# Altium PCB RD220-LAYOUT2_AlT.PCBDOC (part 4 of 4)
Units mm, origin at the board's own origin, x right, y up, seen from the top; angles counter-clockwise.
Board outline 250 x 145 mm, 4 copper layers (TOP, Mid-Layer 1, Mid-Layer 2, BOTTOM), stack 0.711 mm thick; 497 components, 207 nets, 1178 pads, 436 vias.
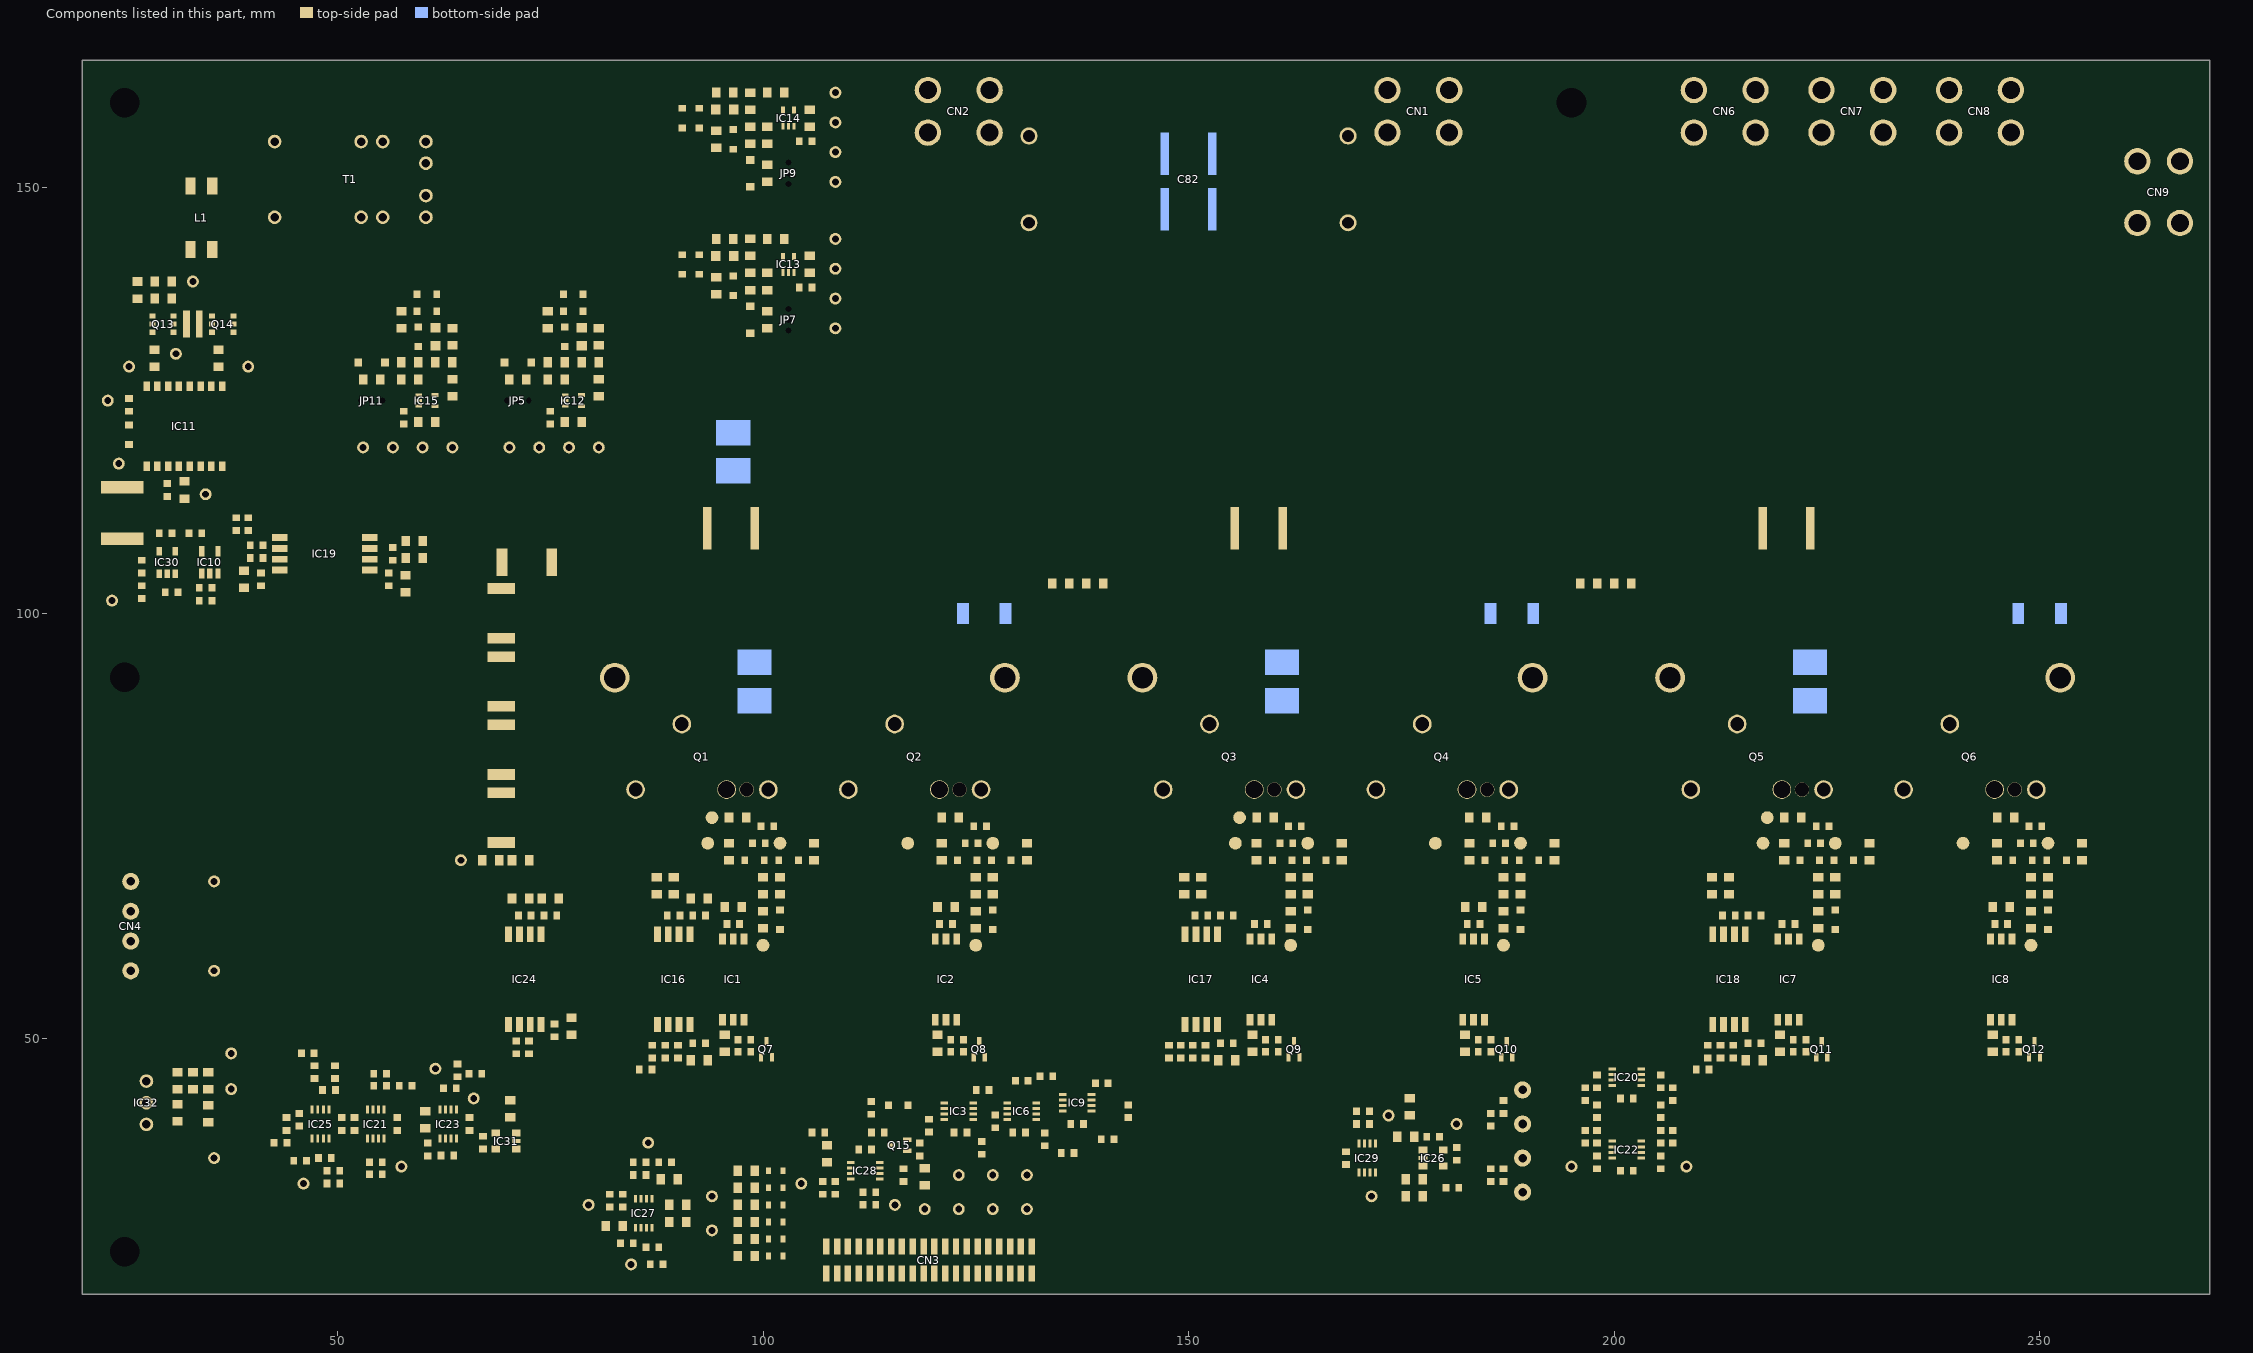
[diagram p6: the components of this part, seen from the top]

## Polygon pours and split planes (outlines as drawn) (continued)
GND_D on TOP "TOP129" (solid, pour order 186): 118.25,37.35 cw(c118.25,37.5) 118.1,37.5 118.1,37.9 cw(c118.25,37.9) 118.25,38.05 119.75,38.05 cw(c119.75,37.9) 119.9,37.9 119.9,37.5 cw(c119.75,37.5) 119.75,37.35
GND_D on TOP "TOP130" (solid, pour order 187): 118.062,37.5 cw(c118.062,37.65) 117.956,37.544 117.6,37.9 116.75,37.9 cw(c116.75,38.05) 116.6,38.05 116.6,38.25 cw(c116.75,38.25) 116.75,38.4 117.688,38.4 cw(c117.688,38.25) 117.794,38.356 118.394,37.756 cw(c118.288,37.65) 118.288,37.5
GND_D on TOP "TOP131" (solid, pour order 188): 116.9,38.7 cw(c116.9,38.85) 116.75,38.85 116.75,39.651 cw(c116.9,39.651) 116.794,39.757 117.368,40.332 117.369,40.333 ccw(c117.05,40.65) 117.5,40.65 117.5,40.85 cw(c117.65,40.85) 117.65,41 118.6,41 cw(c118.6,40.85) 118.75,40.85 118.75,38.85 cw(c118.6,38.85) 118.6,38.7
GND_D on TOP "TOP132" (solid, pour order 189): 117.9,38.7 cw(c117.9,38.85) 117.75,38.85 117.75,39.3 cw(c117.9,39.3) 117.9,39.45 119.7,39.45 cw(c119.7,39.3) 119.85,39.3 119.85,38.85 cw(c119.7,38.85) 119.7,38.7
GND_D on TOP "TOP133" (solid, pour order 190): 118.25,37.6 cw(c118.25,37.75) 118.1,37.75 118.1,38.7 117.4,38.7 cw(c117.4,38.85) 117.25,38.85 117.25,39.85 cw(c117.4,39.85) 117.4,40 118.6,40 cw(c118.6,39.85) 118.75,39.85 118.75,37.75 cw(c118.6,37.75) 118.6,37.6
GND_D on TOP "TOP134" (solid, pour order 191): 25 vertices, not listed, extent 119.15,30.9 121.732,38.35
GND_D on TOP "TOP135" (solid, pour order 192): 22 vertices, not listed, extent 122.3,35 125.701,38.25
GND_D on TOP "TOP136" (solid, pour order 193): 125.35,36.55 cw(c125.5,36.55) 125.5,36.7 126,36.7 cw(c126,36.55) 126.15,36.55 126.15,36.049 cw(c126,36.049) 126.106,35.942 125.606,35.442 cw(c125.5,35.549) 125.35,35.549
GND_D on TOP "TOP137" (solid, pour order 194): 124.211,36.2 cw(c124.211,36.35) 124.105,36.244 123.644,36.705 cw(c123.75,36.811) 123.6,36.811 123.6,37.45 cw(c123.75,37.45) 123.75,37.6 124.25,37.6 cw(c124.25,37.45) 124.4,37.45 124.4,36.85 125.85,36.85 cw(c125.85,36.7) 126,36.7 126,36.35 cw(c125.85,36.35) 125.85,36.2
GND_D on TOP "TOP138" (solid, pour order 195): 123.7,37.05 cw(c123.7,37.2) 123.55,37.2 123.55,40.55 cw(c123.7,40.55) 123.7,40.7 123.8,40.7 cw(c123.8,40.55) 123.95,40.55 123.95,40.4 ccw(c124.3,40.4) 124.23,40.057 cw(c124.2,39.91) 124.35,39.91 124.35,37.2 cw(c124.2,37.2) 124.2,37.05
GND_D on TOP "TOP139" (solid, pour order 196): 137.4,38.3 cw(c137.4,38.45) 137.25,38.45 137.25,41.1 cw(c137.4,41.1) 137.4,41.25 137.782,41.25 cw(c137.782,41.1) 137.908,41.183 ccw(c138.2,41.375) 137.99,41.095 cw(c137.9,40.975) 138.05,40.975 138.05,38.45 cw(c137.9,38.45) 137.9,38.3
GND_D on TOP "TOP140" (solid, pour order 197): 137.25,37 ccw(c136.9,37) 136.9,37.35 cw(c136.9,37.5) 136.78,37.59 ccw(c135.9,38.25) 137,38.25 137,39.1 cw(c137.15,39.1) 137.15,39.25 138.9,39.25 cw(c138.9,39.1) 139.05,39.1 139.05,38.199 cw(c138.9,38.199) 139.006,38.092 137.506,36.593 cw(c137.4,36.699) 137.25,36.699
GND_D on TOP "TOP141" (solid, pour order 198): 137.1,44.35 cw(c137.1,44.5) 136.95,44.5 136.95,45.1 cw(c137.1,45.1) 137.1,45.25 139.15,45.25 cw(c139.15,45.1) 139.3,45.1 139.3,44.5 cw(c139.15,44.5) 139.15,44.35
GND_D on TOP "TOP142" (solid, pour order 199): 23 vertices, not listed, extent 136.55,40.748 138.35,45.3
GND_D on TOP "TOP143" (solid, pour order 200): 130.9,43.45 cw(c130.9,43.6) 130.75,43.6 130.75,45.2 cw(c130.9,45.2) 130.9,45.35 131.4,45.35 cw(c131.4,45.2) 131.55,45.2 131.55,43.6 cw(c131.4,43.6) 131.4,43.45
GND_D on TOP "TOP144" (solid, pour order 201): 132.3,44.2 cw(c132.3,44.35) 132.15,44.35 132.15,45.7 cw(c132.3,45.7) 132.3,45.85 132.8,45.85 cw(c132.8,45.7) 132.95,45.7 132.95,44.549 cw(c132.8,44.549) 132.906,44.443 132.707,44.244 cw(c132.601,44.35) 132.601,44.2
GND_D on TOP "TOP145" (solid, pour order 202): 123,43.55 cw(c123,43.7) 122.85,43.7 122.85,44.15 cw(c123,44.15) 123,44.3 123.088,44.3 ccw(c123.088,44.75) 123.386,44.412 cw(c123.485,44.3) 123.485,44.45 125.1,44.45 cw(c125.1,44.3) 125.25,44.3 125.25,43.7 cw(c125.1,43.7) 125.1,43.55
GND_D on TOP "TOP146" (solid, pour order 203): 31 vertices, not listed, extent 122.543,39.748 124.35,44.45
GND_D on TOP "TOP147" (solid, pour order 204): 127 vertices, not listed, extent 131.6,27.3 175.1,43.8
GND_A on TOP "TOP148" (solid, pour order 205): 249.95,46.5 cw(c249.95,46.65) 249.8,46.65 249.8,48.9 cw(c249.95,48.9) 249.95,49.05 250.15,49.05 cw(c250.15,48.9) 250.3,48.9 250.3,46.65 cw(c250.15,46.65) 250.15,46.5
GND_A on TOP "TOP149" (solid, pour order 206): 45 vertices, not listed, extent 222.55,46.55 243.54,53.1
GND_A on TOP "TOP150" (solid, pour order 207): 224.95,46.55 cw(c224.95,46.7) 224.8,46.7 224.8,48.9 cw(c224.95,48.9) 224.95,49.05 225.15,49.05 cw(c225.15,48.9) 225.3,48.9 225.3,46.7 cw(c225.15,46.7) 225.15,46.55
GND_A on TOP "TOP151" (solid, pour order 208): 187.95,46.65 cw(c187.95,46.8) 187.8,46.8 187.8,48.75 cw(c187.95,48.75) 187.95,48.9 188.15,48.9 cw(c188.15,48.75) 188.3,48.75 188.3,46.8 cw(c188.15,46.8) 188.15,46.65
GND_A on TOP "TOP152" (solid, pour order 209): 49 vertices, not listed, extent 160.401,46.15 181.53,53.1
GND_A on TOP "TOP153" (solid, pour order 210): 162.95,46.5 cw(c162.95,46.65) 162.8,46.65 162.8,48.943 cw(c162.95,48.943) 162.845,49.05 ccw(c162.6,49.3) 162.921,49.16 cw(c163.058,49.1) 163.058,49.25 163.15,49.25 cw(c163.15,49.1) 163.3,49.1 163.3,46.65 cw(c163.15,46.65) 163.15,46.5
GND_A on TOP "TOP154" (solid, pour order 211): 76 vertices, not listed, extent 123.46,44.825 150.05,53.1
GND_A on TOP "TOP155" (solid, pour order 212): 125.95,46.1 cw(c125.95,46.25) 125.8,46.25 125.8,48.943 cw(c125.95,48.943) 125.845,49.05 ccw(c125.6,49.3) 125.943,49.23 cw(c126.09,49.2) 126.09,49.35 126.2,49.35 cw(c126.2,49.2) 126.35,49.2 126.35,46.25 cw(c126.2,46.25) 126.2,46.1
GND_A on TOP "TOP156" (solid, pour order 213): 61 vertices, not listed, extent 98.45,43.65 123.55,53.1
GND_A on TOP "TOP157" (solid, pour order 214): 100.95,46.3 cw(c100.95,46.45) 100.8,46.45 100.8,48.943 cw(c100.95,48.943) 100.845,49.05 ccw(c100.6,49.3) 100.921,49.16 cw(c101.058,49.1) 101.058,49.25 101.15,49.25 cw(c101.15,49.1) 101.3,49.1 101.3,46.45 cw(c101.15,46.45) 101.15,46.3
VREF_2.5V on TOP "TOP158" (solid, pour order 215): 46.35,46.45 cw(c46.35,46.6) 46.2,46.6 46.2,47.1 cw(c46.35,47.1) 46.35,47.25 47.4,47.25 cw(c47.4,47.1) 47.55,47.1 47.55,46.6 cw(c47.4,46.6) 47.4,46.45
VREF_2.5V on TOP "TOP159" (solid, pour order 216): 45.5,47 cw(c45.5,47.15) 45.35,47.15 45.35,48.45 cw(c45.5,48.45) 45.5,48.6 46,48.6 cw(c46,48.45) 46.15,48.45 46.15,47.15 cw(c46,47.15) 46,47
VREF_2.5V on TOP "TOP160" (solid, pour order 217): 44.9,44.55 cw(c44.9,44.7) 44.75,44.7 44.75,46.938 cw(c44.9,46.938) 44.794,47.044 45.256,47.506 cw(c45.362,47.4) 45.362,47.55 46.4,47.55 cw(c46.4,47.4) 46.55,47.4 46.55,44.7 cw(c46.4,44.7) 46.4,44.55
GND_A on TOP "TOP161" (solid, pour order 218): 82 vertices, not listed, extent 194.849,43.748 204.949,48.35
GND_A on TOP "TOP162" (solid, pour order 219): 240 vertices, not listed, extent 185.2,29.8 260.2,53.1
GND_A on TOP "TOP163" (solid, pour order 220): 88 vertices, not listed, extent 187.8,43.4 219.232,53.1
SIGN008161 on TOP "TOP164" (solid, pour order 221): 60.2,39.05 cw(c60.2,39.2) 60.05,39.2 60.05,39.85 cw(c60.2,39.85) 60.2,40 63.088,40 cw(c63.088,39.85) 63.194,39.956 63.456,39.694 cw(c63.35,39.588) 63.5,39.588 63.5,39.2 cw(c63.35,39.2) 63.35,39.05
GND_A on TOP "TOP165" (solid, pour order 222): 41 vertices, not listed, extent 56.35,34.9 59.85,44.245
GND_A on TOP "TOP166" (solid, pour order 223): 66.8,38.35 cw(c66.8,38.5) 66.65,38.5 66.65,39.65 cw(c66.8,39.65) 66.8,39.8 67.4,39.8 cw(c67.4,39.65) 67.55,39.65 67.55,38.5 cw(c67.4,38.5) 67.4,38.35
GND_A on TOP "TOP167" (solid, pour order 224): 182 vertices, not listed, extent 62.7,39.25 102.35,53.1
GND_D on TOP "TOP168" (solid, pour order 225): 34.35,38.45 cw(c34.35,38.6) 34.2,38.6 34.2,40.35 cw(c34.35,40.35) 34.35,40.5 35.05,40.5 cw(c35.05,40.35) 35.2,40.35 35.2,38.6 cw(c35.05,38.6) 35.05,38.45
GND_D on TOP "TOP169" (solid, pour order 226): 34.55,39.8 cw(c34.55,39.95) 34.4,39.95 34.4,40.55 cw(c34.55,40.55) 34.55,40.7 36.25,40.7 cw(c36.25,40.55) 36.4,40.55 36.4,39.95 cw(c36.25,39.95) 36.25,39.8
GND_A on TOP "TOP170" (solid, pour order 227): 32.25,41.8 cw(c32.25,41.95) 32.1,41.95 32.1,42.888 cw(c32.25,42.888) 32.144,42.994 32.406,43.256 cw(c32.512,43.15) 32.512,43.3 33.75,43.3 cw(c33.75,43.15) 33.9,43.15 33.9,41.95 cw(c33.75,41.95) 33.75,41.8
GND_A on TOP "TOP171" (solid, pour order 228): 95 vertices, not listed, extent 35.7,30.976 65.8,45.05
GND_D on TOP "TOP174" (solid, pour order 231): 28 vertices, not listed, extent 130.05,39.75 132.95,44.85
VREF_2.5V on TOP "TOP175" (solid, pour order 232): 33 vertices, not listed, extent 60.042,42.3 62.5,46.75
GND_D on TOP "TOP176" (solid, pour order 233): 29 vertices, not listed, extent 180.75,30.85 184.75,36.154
GND_D on TOP "TOP177" (solid, pour order 234): 181.5,30.85 cw(c181.5,31) 181.35,31 181.35,33.75 cw(c181.5,33.75) 181.5,33.9 181.85,33.9 cw(c181.85,33.75) 182,33.75 182,31 cw(c181.85,31) 181.85,30.85
GND_D on TOP "TOP178" (solid, pour order 235): 181.5,32.2 cw(c181.5,32.35) 181.35,32.35 181.35,32.65 cw(c181.5,32.65) 181.5,32.8 183.55,32.8 cw(c183.55,32.65) 183.7,32.65 183.7,32.35 cw(c183.55,32.35) 183.55,32.2
GND_D on TOP "TOP180" (solid, pour order 237): 224 vertices, not listed, extent 21,21 107.15,41.1
GND_D on TOP "TOP181" (solid, pour order 238): 93 vertices, not listed, extent 102.5,27.85 112.6,38.2
IWN on TOP "TOP183" (solid, pour order 240): 221.75,96 cw(c221.75,96.15) 221.6,96.15 221.6,103.75 cw(c221.75,103.75) 221.75,103.9 232.9,103.9 237.25,108.25 237.25,163.399 cw(c239.375,161.5) 237.448,163.6 248.552,163.6 cw(c246.625,161.5) 248.75,163.399 248.75,102.812 cw(c248.6,102.812) 248.706,102.706 242.044,96.044 cw(c241.938,96.15) 241.938,96
GND_F on TOP "TOP184" (solid, pour order 241): 267.15,139.05 cw(c267.15,139.2) 267,139.2 267,140 ccw(c263.6,140) 263.6,143.4 255.75,143.4 cw(c255.75,143.55) 255.6,143.55 255.6,163.85 cw(c255.75,163.85) 255.75,164 268.85,164 cw(c268.85,163.85) 269,163.85 269,139.2 cw(c268.85,139.2) 268.85,139.05
VP_DC on TOP "TOP185" (solid, pour order 242): 57 vertices, not listed, extent 160,85.9 217.95,164
GND_A on TOP "TOP12" (solid, pour order 69): 25.05,138.5 cw(c25.05,138.65) 24.9,138.65 24.9,139.15 cw(c25.05,139.15) 25.05,139.3 26.55,139.3 cw(c26.55,139.15) 26.7,139.15 26.7,138.65 cw(c26.55,138.65) 26.55,138.5
GND_A on TOP "TOP13" (solid, pour order 70): 28.25,138.7 cw(c28.25,138.85) 28.1,138.85 28.1,140.35 cw(c28.25,140.35) 28.25,140.5 28.85,140.5 cw(c28.85,140.35) 29,140.35 29,138.85 cw(c28.85,138.85) 28.85,138.7
GND_A on TOP "TOP14" (solid, pour order 71): 26.15,138.8 cw(c26.15,138.95) 26,138.95 26,140.85 cw(c26.15,140.85) 26.15,141 26.75,141 cw(c26.75,140.85) 26.9,140.85 26.9,138.95 cw(c26.75,138.95) 26.75,138.8
GND_A on TOP "TOP15" (solid, pour order 72): 37.8,132.75 cw(c37.8,132.9) 37.65,132.9 37.65,133.2 cw(c37.8,133.2) 37.8,133.35 39.25,133.35 cw(c39.25,133.2) 39.4,133.2 39.4,132.9 cw(c39.25,132.9) 39.25,132.75
GND_A on TOP "TOP16" (solid, pour order 73): 34.95,115.25 cw(c34.95,115.4) 34.8,115.4 34.8,118.6 cw(c34.95,118.6) 34.95,118.75 35.4,118.75 cw(c35.4,118.6) 35.55,118.6 35.55,115.4 cw(c35.4,115.4) 35.4,115.25
GND_A on TOP "TOP17" (solid, pour order 74): 31.7,112.3 cw(c31.7,112.45) 31.55,112.45 31.55,113.45 cw(c31.7,113.45) 31.7,113.6 32.45,113.6 cw(c32.45,113.45) 32.6,113.45 32.6,112.45 cw(c32.45,112.45) 32.45,112.3
GND_A on TOP "TOP18" (solid, pour order 75): 28.8,113.55 cw(c28.8,113.7) 28.65,113.7 28.65,114 cw(c28.8,114) 28.8,114.15 30,114.15 cw(c30,114) 30.15,114 30.15,113.7 cw(c30,113.7) 30,113.55
GND_A on TOP "TOP19" (solid, pour order 76): 29.85,112.55 cw(c29.85,112.7) 29.7,112.7 29.7,113.65 cw(c29.85,113.65) 29.85,113.8 30.3,113.8 cw(c30.3,113.65) 30.45,113.65 30.45,112.7 cw(c30.3,112.7) 30.3,112.55
GND_A on TOP "TOP20" (solid, pour order 77): 42.033,108.5 cw(c42.033,108.65) 41.903,108.575 ccw(c41.6,108.4) 41.635,108.748 cw(c41.65,108.898) 41.5,108.898 41.5,109.15 cw(c41.65,109.15) 41.65,109.3 44.5,109.3 cw(c44.5,109.15) 44.65,109.15 44.65,108.65 cw(c44.5,108.65) 44.5,108.5
GND_A on TOP "TOP21" (solid, pour order 78): 38.6,101.2 cw(c38.6,101.35) 38.45,101.35 38.45,103.1 cw(c38.6,103.1) 38.6,103.25 39.35,103.25 cw(c39.35,103.1) 39.5,103.1 39.5,101.35 cw(c39.35,101.35) 39.35,101.2
GND_A on TOP "TOP77" (solid, pour order 134): 26.3,138.5 cw(c26.3,138.65) 26.15,138.65 26.15,139.25 cw(c26.3,139.25) 26.3,139.4 28.45,139.4 cw(c28.45,139.25) 28.6,139.25 28.6,138.65 cw(c28.45,138.65) 28.45,138.5
GND_A on TOP "TOP78" (solid, pour order 135): 29.85,113.35 cw(c29.85,113.5) 29.7,113.5 29.7,114 cw(c29.85,114) 29.85,114.15 31.038,114.15 cw(c31.038,114) 31.144,114.106 31.3,113.95 32.1,113.95 cw(c32.1,113.8) 32.25,113.8 32.25,113.5 cw(c32.1,113.5) 32.1,113.35
VDD20_A on TOP "TOP81" (solid, pour order 138): 29.05,133.7 cw(c29.05,133.85) 28.9,133.85 28.9,135.1 cw(c29.05,135.1) 29.05,135.25 29.95,135.25 cw(c29.95,135.1) 30.1,135.1 30.1,133.85 cw(c29.95,133.85) 29.95,133.7
SIGN00537 on TOP "TOP82" (solid, pour order 139): 36.05,133.7 cw(c36.05,133.85) 35.9,133.85 35.9,135.1 cw(c36.05,135.1) 36.05,135.25 36.95,135.25 cw(c36.95,135.1) 37.1,135.1 37.1,133.85 cw(c36.95,133.85) 36.95,133.7
GND_A on TOP "TOP91" (solid, pour order 148): 25.853,134.046 cw(c25.853,133.896) 25.987,133.963 cw(c25.853,133.896) 26.003,133.896 cw(c25.853,133.896) 25.853,134.046
GND_A on TOP "TOP92" (solid, pour order 149): 29.6,101.4 cw(c29.6,101.55) 29.45,101.55 29.45,102.65 cw(c29.6,102.65) 29.6,102.8 30,102.8 cw(c30,102.65) 30.15,102.65 30.15,101.55 cw(c30,101.55) 30,101.4
GND_A on TOP "TOP93" (solid, pour order 150): 26.8,100.6 cw(c26.8,100.75) 26.65,100.75 26.65,101.9 cw(c26.8,101.9) 26.8,102.05 27.2,102.05 cw(c27.2,101.9) 27.35,101.9 27.35,100.75 cw(c27.2,100.75) 27.2,100.6
GND_A on TOP "TOP94" (solid, pour order 151): 28.65,102.15 cw(c28.65,102.3) 28.5,102.3 28.5,102.5 cw(c28.65,102.5) 28.65,102.65 28.8,102.65 28.956,102.806 cw(c29.062,102.7) 29.062,102.85 30,102.85 cw(c30,102.7) 30.15,102.7 30.15,102.3 cw(c30,102.3) 30,102.15
GND_A on TOP "TOP95" (solid, pour order 152): 25.85,101.45 cw(c25.85,101.6) 25.7,101.6 25.7,102 cw(c25.85,102) 25.85,102.15 28.15,102.15 cw(c28.15,102) 28.3,102 28.3,101.6 cw(c28.15,101.6) 28.15,101.45
GND_A on TOP "TOP96" (solid, pour order 153): 19 vertices, not listed, extent 31.7,103.8 35.8,107.9
GND_A on TOP "TOP97" (solid, pour order 154): 34.85,104.5 cw(c34.85,104.65) 34.7,104.65 34.7,105.95 cw(c34.85,105.95) 34.85,106.1 35.15,106.1 cw(c35.15,105.95) 35.3,105.95 35.3,104.65 cw(c35.15,104.65) 35.15,104.5
GND_A on TOP "TOP98" (solid, pour order 155): 37.9,102.6 cw(c37.9,102.75) 37.75,102.75 37.75,103.35 cw(c37.9,103.35) 37.9,103.5 39.65,103.5 39.756,103.606 cw(c39.862,103.5) 39.862,103.65 42.15,103.65 cw(c42.15,103.5) 42.3,103.5 42.3,103.1 cw(c42.15,103.1) 42.15,102.95 39.85,102.95 39.544,102.644 cw(c39.438,102.75) 39.438,102.6
GND_A on TOP "TOP99" (solid, pour order 156): 31.75,113.1 cw(c31.75,113.25) 31.6,113.25 31.6,113.8 cw(c31.75,113.8) 31.75,113.95 33.05,113.95 cw(c33.05,113.8) 33.2,113.8 33.2,113.25 cw(c33.05,113.25) 33.05,113.1
GND_A on TOP "TOP106" (solid, pour order 163): 40.85,101.8 cw(c40.85,101.95) 40.7,101.95 40.7,103.35 cw(c40.85,103.35) 40.85,103.5 41.15,103.5 cw(c41.15,103.35) 41.3,103.35 41.3,101.95 cw(c41.15,101.95) 41.15,101.8
GND_A on TOP "TOP107" (solid, pour order 164): 32 vertices, not listed, extent 26.25,118.173 35.995,125.827
SIGN00514 on TOP "TOP108" (solid, pour order 165): 28.05,130.5 cw(c28.05,130.65) 27.9,130.65 27.9,133.2 cw(c28.05,133.2) 28.05,133.35 28.95,133.35 cw(c28.95,133.2) 29.1,133.2 29.1,130.65 cw(c28.95,130.65) 28.95,130.5
SIGN00515 on TOP "TOP109" (solid, pour order 166): 35.55,130.55 cw(c35.55,130.7) 35.4,130.7 35.4,131.5 34.944,131.956 cw(c35.05,132.062) 34.9,132.062 34.9,133.2 cw(c35.05,133.2) 35.05,133.35 35.559,133.35 cw(c35.559,133.2) 35.7,133.25 36.556,132.394 cw(c36.45,132.288) 36.6,132.288 36.6,130.7 cw(c36.45,130.7) 36.45,130.55
SIGN00541 on TOP "TOP110" (solid, pour order 167): 30.55,131.4 cw(c30.55,131.55) 30.4,131.55 30.4,132.29 cw(c30.55,132.29) 30.55,132.44 31.05,132.44 ccw(c31.05,132.79) 31.4,132.79 31.4,133.2 cw(c31.55,133.2) 31.55,133.35 32.5,133.35 cw(c32.5,133.2) 32.65,133.2 32.65,131.55 cw(c32.5,131.55) 32.5,131.4
SIGN00541 on TOP "TOP111" (solid, pour order 168): 20 vertices, not listed, extent 30.3,127.571 32.4,131.7
GND_A on TOP "TOP172" (solid, pour order 229): 21.5,108.2 cw(c21.5,108.35) 21.35,108.35 21.35,109.35 cw(c21.5,109.35) 21.5,109.5 27.85,109.5 cw(c27.85,109.35) 28,109.35 28,108.35 cw(c27.85,108.35) 27.85,108.2
GND_A on TOP "TOP173" (solid, pour order 230): 22.55,107.25 cw(c22.55,107.4) 22.4,107.4 22.4,109 cw(c22.55,109) 22.55,109.15 26.85,109.15 cw(c26.85,109) 27,109 27,107.4 cw(c26.85,107.4) 26.85,107.25
GND_D on Mid-Layer 1 "MID1198" (solid, pour order 56): 69 vertices, not listed, extent 21,21 141.9,47.1
GND_F on Mid-Layer 1 "MID1186" (solid, pour order 44): 145,21 cw(c145,25) 148.928,25.757 ccw(c152.266,26.4) 152.266,23 157.35,23 cw(c157.35,22.85) 157.5,22.85 157.5,21.15 cw(c157.35,21.15) 157.35,21
GND_F on Mid-Layer 1 "MID1187" (solid, pour order 45): 254.35,21 cw(c254.35,21.15) 254.2,21.15 254.2,22.85 cw(c254.35,22.85) 254.35,23 257.734,23 ccw(c257.734,26.4) 261.072,25.757 cw(c265,25) 264.243,28.928 ccw(c263.6,32.266) 267,32.266 267,33.55 cw(c267.15,33.55) 267.15,33.7 268.85,33.7 cw(c268.85,33.55) 269,33.55 269,21.15 cw(c268.85,21.15) 268.85,21
GND_F on Mid-Layer 1 "MID1188" (solid, pour order 46): 267.03,86 cw(c267.03,86.15) 266.885,86.111 ccw(c263.6,85.234) 264.243,88.572 cw(c265,92.5) 264.243,96.428 ccw(c263.6,99.766) 267,99.766 267,99.85 cw(c267.15,99.85) 267.15,100 268.85,100 cw(c268.85,99.85) 269,99.85 269,86.15 cw(c268.85,86.15) 268.85,86
GND_U on Mid-Layer 1 "MID1189" (solid, pour order 47): 39 vertices, not listed, extent 92.3,64.05 106.8,77.9
GND_B on Mid-Layer 1 "MID1190" (solid, pour order 48): 23 vertices, not listed, extent 117.05,64.05 131.8,77.9
GND_B on Mid-Layer 1 "MID1191" (solid, pour order 49): 23 vertices, not listed, extent 179.05,64.05 193.8,77.9
GND_B on Mid-Layer 1 "MID1192" (solid, pour order 50): 23 vertices, not listed, extent 241.05,64.05 255.8,77.9
GND_V on Mid-Layer 1 "MID1193" (solid, pour order 51): 39 vertices, not listed, extent 154.3,64.05 168.8,77.9
GND_W on Mid-Layer 1 "MID1194" (solid, pour order 52): 39 vertices, not listed, extent 216.3,64.05 230.8,77.9
GND_A on Mid-Layer 1 "MID1195" (solid, pour order 53): 126.15,23.4 cw(c126.15,23.55) 126,23.55 126,24.55 cw(c126.15,24.55) 126.15,24.7 130.724,24.7 133.068,27.044 ccw(c132.75,27.362) 133.2,27.362 133.2,27.65 cw(c133.35,27.65) 133.35,27.8 134.05,27.8 cw(c134.05,27.65) 134.2,27.65 134.2,23.55 cw(c134.05,23.55) 134.05,23.4
GND_D on Mid-Layer 1 "MID1196" (solid, pour order 54): 24 vertices, not listed, extent 143.5,29.8 185.109,43.8
GND_A on Mid-Layer 1 "MID1197" (solid, pour order 55): 104 vertices, not listed, extent 21,29.8 260.2,164
GND_F on Mid-Layer 1 "MID1199" (solid, pour order 57): 17 vertices, not listed, extent 255.6,139.1 269,164
GND_D on Mid-Layer 2 "MID2217" (solid, pour order 42): 183 vertices, not listed, extent 21,21 117.8,43.8
GND_A on Mid-Layer 2 "MID2216" (solid, pour order 41): 143 vertices, not listed, extent 21,29.8 260.2,164
GND_D on Mid-Layer 2 "MID2215" (solid, pour order 40): 50 vertices, not listed, extent 116.75,28.3 185.109,45.5
GND_F on Mid-Layer 2 "MID2200" (solid, pour order 25): 145,21 cw(c145,25) 148.928,25.757 ccw(c152.266,26.4) 152.266,23 157.35,23 cw(c157.35,22.85) 157.5,22.85 157.5,21.15 cw(c157.35,21.15) 157.35,21
GND_F on Mid-Layer 2 "MID2201" (solid, pour order 26): 254.35,21 cw(c254.35,21.15) 254.2,21.15 254.2,22.85 cw(c254.35,22.85) 254.35,23 257.734,23 ccw(c257.734,26.4) 261.072,25.757 cw(c265,25) 264.243,28.928 ccw(c263.6,32.266) 267,32.266 267,33.55 cw(c267.15,33.55) 267.15,33.7 268.85,33.7 cw(c268.85,33.55) 269,33.55 269,21.15 cw(c268.85,21.15) 268.85,21
GND_F on Mid-Layer 2 "MID2202" (solid, pour order 27): 267.03,86 cw(c267.03,86.15) 266.885,86.111 ccw(c263.6,85.234) 264.243,88.572 cw(c265,92.5) 264.243,96.428 ccw(c263.6,99.766) 267,99.766 267,99.85 cw(c267.15,99.85) 267.15,100 268.85,100 cw(c268.85,99.85) 269,99.85 269,86.15 cw(c268.85,86.15) 268.85,86
IVN on Mid-Layer 2 "MID2203" (solid, pour order 28): 159.75,95.9 cw(c159.75,96.05) 159.6,96.05 159.6,103.75 cw(c159.75,103.75) 159.75,103.9 170.65,103.9 173.444,106.694 cw(c173.55,106.588) 173.656,106.694 175.756,104.594 cw(c175.65,104.488) 175.8,104.488 175.8,98.812 cw(c175.65,98.812) 175.756,98.706 172.994,95.944 cw(c172.888,96.05) 172.888,95.9
IUN on Mid-Layer 2 "MID2204" (solid, pour order 29): 97.85,96 cw(c97.85,96.15) 97.7,96.15 97.7,103.75 cw(c97.85,103.75) 97.85,103.9 110.708,103.9 113.852,107.044 cw(c113.958,106.938) 114.064,107.044 117.256,103.852 cw(c117.15,103.746) 117.3,103.746 117.3,100.212 cw(c117.15,100.212) 117.256,100.106 113.194,96.044 cw(c113.088,96.15) 113.088,96
IUN on Mid-Layer 2 "MID2205" (solid, pour order 30): 137.731,130.669 cw(c137.837,130.775) 137.732,130.882 145.156,138.306 cw(c145.262,138.2) 145.262,138.35 153.85,138.35 cw(c153.85,138.2) 154,138.2 154,131.2 cw(c153.85,131.2) 153.85,131.05 148.25,131.05 142.906,125.706 cw(c142.8,125.812) 142.694,125.706
IVN on Mid-Layer 2 "MID2206" (solid, pour order 31): 212.656,118.044 cw(c212.762,118.15) 212.656,118.256 212.657,118.257 223.856,129.456 cw(c223.962,129.35) 223.962,129.5 230.65,129.5 cw(c230.65,129.35) 230.8,129.35 230.8,121.65 cw(c230.65,121.65) 230.65,121.5 226.2,121.5 217.806,113.106 cw(c217.7,113.212) 217.594,113.106
IUP on Mid-Layer 2 "MID2207" (solid, pour order 32): 114.55,83.9 cw(c114.55,84.05) 114.4,84.05 114.4,87.95 cw(c114.55,87.95) 114.55,88.1 116.538,88.1 cw(c116.538,87.95) 116.644,88.056 117.256,87.444 cw(c117.15,87.338) 117.3,87.338 117.3,84.05 cw(c117.15,84.05) 117.15,83.9
IVP on Mid-Layer 2 "MID2208" (solid, pour order 33): 176.55,83.9 cw(c176.55,84.05) 176.4,84.05 176.4,87.95 cw(c176.55,87.95) 176.55,88.1 178.538,88.1 cw(c178.538,87.95) 178.644,88.056 179.256,87.444 cw(c179.15,87.338) 179.3,87.338 179.3,84.05 cw(c179.15,84.05) 179.15,83.9
IWP on Mid-Layer 2 "MID2209" (solid, pour order 34): 238.55,83.9 cw(c238.55,84.05) 238.4,84.05 238.4,87.95 cw(c238.55,87.95) 238.55,88.1 240.538,88.1 cw(c240.538,87.95) 240.644,88.056 241.256,87.444 cw(c241.15,87.338) 241.3,87.338 241.3,84.05 cw(c241.15,84.05) 241.15,83.9
IUP on Mid-Layer 2 "MID2210" (solid, pour order 35): 34 vertices, not listed, extent 92.45,77.45 115.86,91.2
IVP on Mid-Layer 2 "MID2211" (solid, pour order 36): 34 vertices, not listed, extent 154.45,77.45 177.86,91.2
IWP on Mid-Layer 2 "MID2212" (solid, pour order 37): 34 vertices, not listed, extent 216.45,77.45 239.86,91.2
GND_A on Mid-Layer 2 "MID2213" (solid, pour order 38): 126.15,23.4 cw(c126.15,23.55) 126,23.55 126,24.55 cw(c126.15,24.55) 126.15,24.7 130.724,24.7 132.98,26.956 cw(c133.086,26.85) 133.086,27 134.05,27 cw(c134.05,26.85) 134.2,26.85 134.2,23.55 cw(c134.05,23.55) 134.05,23.4
GND_D on Mid-Layer 2 "MID2214" (solid, pour order 39): 55 vertices, not listed, extent 115.75,21 135.332,30
GND_F on Mid-Layer 2 "MID2218" (solid, pour order 43): 17 vertices, not listed, extent 255.6,139.1 269,164
GND_D on BOTTOM "BOTTOM235" (solid, pour order 18): 267 vertices, not listed, extent 21,21 185.109,45.5
GND_F on BOTTOM "BOTTOM219" (solid, pour order 2): 145,21 cw(c145,25) 148.928,25.757 ccw(c152.266,26.4) 152.266,23 157.35,23 cw(c157.35,22.85) 157.5,22.85 157.5,21.15 cw(c157.35,21.15) 157.35,21
GND_F on BOTTOM "BOTTOM220" (solid, pour order 3): 254.35,21 cw(c254.35,21.15) 254.2,21.15 254.2,22.85 cw(c254.35,22.85) 254.35,23 257.734,23 ccw(c257.734,26.4) 261.072,25.757 cw(c265,25) 264.243,28.928 ccw(c263.6,32.266) 267,32.266 267,33.55 cw(c267.15,33.55) 267.15,33.7 268.85,33.7 cw(c268.85,33.55) 269,33.55 269,21.15 cw(c268.85,21.15) 268.85,21
GND_F on BOTTOM "BOTTOM221" (solid, pour order 4): 267.03,86 cw(c267.03,86.15) 266.885,86.111 ccw(c263.6,85.234) 264.243,88.572 cw(c265,92.5) 264.243,96.428 ccw(c263.6,99.766) 267,99.766 267,99.85 cw(c267.15,99.85) 267.15,100 268.85,100 cw(c268.85,99.85) 269,99.85 269,86.15 cw(c268.85,86.15) 268.85,86
IVN on BOTTOM "BOTTOM222" (solid, pour order 5): 157.15,92.8 cw(c157.15,92.95) 157,92.95 157,103.65 cw(c157.15,103.65) 157.15,103.8 164.8,103.8 cw(c164.8,103.3) 165.3,103.3 165.3,92.95 cw(c165.15,92.95) 165.15,92.8 161.6,92.8 cw(c161.6,92.95) 161.45,92.95 161.45,94.25 ccw(c161,94.25) 160.55,94.25 160.55,92.95 cw(c160.4,92.95) 160.4,92.8
IWN on BOTTOM "BOTTOM223" (solid, pour order 6): 219.15,92.8 cw(c219.15,92.95) 219,92.95 219,103.65 cw(c219.15,103.65) 219.15,103.8 226.8,103.8 cw(c226.8,103.3) 227.3,103.3 227.3,92.95 cw(c227.15,92.95) 227.15,92.8
IUN on BOTTOM "BOTTOM224" (solid, pour order 7): 95.15,92.8 cw(c95.15,92.95) 95,92.95 95,103.65 cw(c95.15,103.65) 95.15,103.8 102.8,103.8 cw(c102.8,103.3) 103.3,103.3 103.3,92.95 cw(c103.15,92.95) 103.15,92.8
IUP on BOTTOM "BOTTOM225" (solid, pour order 8): 114.55,83.9 cw(c114.55,84.05) 114.4,84.05 114.4,87.95 cw(c114.55,87.95) 114.55,88.1 116.538,88.1 cw(c116.538,87.95) 116.644,88.056 117.255,87.445 117.256,87.444 cw(c117.15,87.338) 117.3,87.338 117.3,86.262 cw(c117.15,86.262) 117.256,86.156 115.044,83.944 cw(c114.938,84.05) 114.938,83.9
IVP on BOTTOM "BOTTOM226" (solid, pour order 9): 176.55,83.9 cw(c176.55,84.05) 176.4,84.05 176.4,87.95 cw(c176.55,87.95) 176.55,88.1 178.538,88.1 cw(c178.538,87.95) 178.644,88.056 179.255,87.445 179.256,87.444 cw(c179.15,87.338) 179.3,87.338 179.3,86.262 cw(c179.15,86.262) 179.256,86.156 177.044,83.944 cw(c176.938,84.05) 176.938,83.9
IVP on BOTTOM "BOTTOM227" (solid, pour order 10): 30 vertices, not listed, extent 154.45,74 177.86,91.2
IWP on BOTTOM "BOTTOM228" (solid, pour order 11): 238.55,83.9 cw(c238.55,84.05) 238.4,84.05 238.4,87.95 cw(c238.55,87.95) 238.55,88.1 240.538,88.1 cw(c240.538,87.95) 240.644,88.056 241.255,87.445 241.256,87.444 cw(c241.15,87.338) 241.3,87.338 241.3,86.262 cw(c241.15,86.262) 241.256,86.156 239.044,83.944 cw(c238.938,84.05) 238.938,83.9
IWP on BOTTOM "BOTTOM229" (solid, pour order 12): 30 vertices, not listed, extent 216.45,74 239.86,91.2
IDCP on BOTTOM "BOTTOM230" (solid, pour order 13): 134 vertices, not listed, extent 94.5,78.7 249.05,118.25
IUP on BOTTOM "BOTTOM231" (solid, pour order 14): 30 vertices, not listed, extent 92.45,74 115.86,91.2
GND_A on BOTTOM "BOTTOM232" (solid, pour order 15): 240 vertices, not listed, extent 33.7,31.65 153.142,53.5
GND_A on BOTTOM "BOTTOM233" (solid, pour order 16): 541 vertices, not listed, extent 21,29.8 260.2,164
GND_A on BOTTOM "BOTTOM234" (solid, pour order 17): 26 vertices, not listed, extent 126.135,23.401 134.2,27
GND_D on BOTTOM "BOTTOM236" (solid, pour order 19): 28 vertices, not listed, extent 150.562,29.8 182.2,38.064
GND_DC on BOTTOM "BOTTOM237" (solid, pour order 20): 39 vertices, not listed, extent 94.5,119.75 147.7,164
VP_DC on BOTTOM "BOTTOM238" (solid, pour order 21): 45 vertices, not listed, extent 152.3,144.8 182.8,164
IUN on BOTTOM "BOTTOM239" (solid, pour order 22): 25 vertices, not listed, extent 146.3,127 218.75,163.6
IVN on BOTTOM "BOTTOM240" (solid, pour order 23): 25 vertices, not listed, extent 222.25,121.8 233.75,163.6
GND_F on BOTTOM "BOTTOM241" (solid, pour order 24): 267.15,139.15 cw(c267.15,139.3) 267,139.3 267,140 ccw(c263.6,140) 263.6,143.4 255.75,143.4 cw(c255.75,143.55) 255.6,143.55 255.6,163.85 cw(c255.75,163.85) 255.75,164 268.85,164 cw(c268.85,163.85) 269,163.85 269,139.3 cw(c268.85,139.3) 268.85,139.15
no net on Top Solder "TOPSOLDER254" (solid, pour order 0): 23.05,160 ccw(c25,160) 26.95,160 ccw(c25,160)
no net on Top Solder "TOPSOLDER255" (solid, pour order 0): 193.05,160 ccw(c195,160) 196.95,160 ccw(c195,160)
no net on Top Solder "TOPSOLDER256" (solid, pour order 0): 23.05,25 ccw(c25,25) 26.95,25 ccw(c25,25)
no net on Top Solder "TOPSOLDER257" (solid, pour order 0): 23.05,92.5 ccw(c25,92.5) 26.95,92.5 ccw(c25,92.5)
no net on Top Solder "TOPSOLDER258" (solid, pour order 0): 58,150.3 cw(c58,151) 57.3,151 cw(c58,151) 58,151.7 63,151.7 cw(c63,151) 63.7,151 cw(c63,151) 63,150.3
no net on Top Solder "TOPSOLDER259" (solid, pour order 0): 124.423,91.606 cw(c125.07,91.874) 124.37,91.874 124.37,95.907 cw(c125.07,95.907) 125.77,95.907 125.77,92.013 127.26,88.415 cw(c126.614,88.147) 125.967,87.879
no net on Top Solder "TOPSOLDER260" (solid, pour order 0): 186.423,91.606 cw(c187.07,91.874) 186.37,91.874 186.37,95.907 cw(c187.07,95.907) 187.77,95.907 187.77,92.013 189.26,88.415 cw(c188.614,88.147) 187.967,87.879
no net on Top Solder "TOPSOLDER261" (solid, pour order 0): 179.66,87.438 178.383,90.52 cw(c179.03,90.787) 179.677,91.055 181.007,87.845 cw(c180.36,87.577) 181.06,87.577 181.06,84.102 cw(c180.36,84.102) 179.66,84.102
no net on Top Solder "TOPSOLDER262" (solid, pour order 0): 241.66,87.438 240.383,90.52 cw(c241.03,90.787) 241.677,91.055 243.007,87.845 cw(c242.36,87.577) 243.06,87.577 243.06,84.102 cw(c242.36,84.102) 241.66,84.102
no net on Top Solder "TOPSOLDER263" (solid, pour order 0): 248.423,91.606 cw(c249.07,91.874) 248.37,91.874 248.37,95.907 cw(c249.07,95.907) 249.77,95.907 249.77,92.013 251.26,88.415 cw(c250.614,88.147) 249.967,87.879
no net on Top Solder "TOPSOLDER264" (solid, pour order 0): 117.66,87.438 116.383,90.52 cw(c117.03,90.787) 117.677,91.055 119.007,87.845 cw(c118.36,87.577) 119.06,87.577 119.06,84.102 cw(c118.36,84.102) 117.66,84.102
no net on Bottom Solder "BOTTOMSOLDER265" (solid, pour order 0): 123.775,156.5 ccw(c126.625,156.5) 129.475,156.5 ccw(c126.625,156.5)
no net on Bottom Solder "BOTTOMSOLDER266" (solid, pour order 0): 128.95,156.1 ccw(c131.25,156.1) 133.55,156.1 ccw(c131.25,156.1)
no net on Bottom Solder "BOTTOMSOLDER267" (solid, pour order 0): 128.95,145.9 ccw(c131.25,145.9) 133.55,145.9 ccw(c131.25,145.9)
no net on Bottom Solder "BOTTOMSOLDER268" (solid, pour order 0): 166.45,156.1 ccw(c168.75,156.1) 171.05,156.1 ccw(c168.75,156.1)
no net on Bottom Solder "BOTTOMSOLDER269" (solid, pour order 0): 127.993,164 cw(c126.625,161.5) 125.257,164
no net on Bottom Solder "BOTTOMSOLDER270" (solid, pour order 0): 117.2,163.342 cw(c119.375,161.5) 118.007,164 120.743,164 cw(c119.375,161.5) 117.2,159.658
no net on Bottom Solder "BOTTOMSOLDER271" (solid, pour order 0): 117.448,154.4 cw(c119.375,156.5) 117.2,154.658 117.2,158.342 cw(c119.375,156.5) 121.302,154.4
no net on Bottom Solder "BOTTOMSOLDER272" (solid, pour order 0): 174.743,164 cw(c173.375,161.5) 172.007,164
no net on Bottom Solder "BOTTOMSOLDER273" (solid, pour order 0): 181.993,164 cw(c180.625,161.5) 182.8,163.342 182.8,159.658 cw(c180.625,161.5) 179.257,164
no net on Bottom Solder "BOTTOMSOLDER274" (solid, pour order 0): 178.698,154.4 cw(c180.625,156.5) 182.8,158.342 182.8,154.658 cw(c180.625,156.5) 182.552,154.4
no net on Bottom Solder "BOTTOMSOLDER275" (solid, pour order 0): 171.448,154.4 cw(c173.375,156.5) 175.302,154.4
no net on Bottom Solder "BOTTOMSOLDER276" (solid, pour order 0): 166.73,144.8 cw(c168.75,145.9) 170.77,144.8
no net on Bottom Solder "BOTTOMSOLDER277" (solid, pour order 0): 207.4,163.555 207.448,163.6 211.302,163.6 cw(c209.375,161.5) 207.4,159.445
no net on Bottom Solder "BOTTOMSOLDER278" (solid, pour order 0): 207.4,158.555 cw(c209.375,156.5) 207.4,154.445
no net on Bottom Solder "BOTTOMSOLDER279" (solid, pour order 0): 218.552,163.6 cw(c216.625,161.5) 218.75,163.399 218.75,159.601 cw(c216.625,161.5) 214.698,163.6
no net on Bottom Solder "BOTTOMSOLDER280" (solid, pour order 0): 218.75,154.601 cw(c216.625,156.5) 218.75,158.399
no net on Bottom Solder "BOTTOMSOLDER281" (solid, pour order 0): 222.25,158.399 cw(c224.375,156.5) 222.25,154.601
no net on Bottom Solder "BOTTOMSOLDER282" (solid, pour order 0): 222.25,163.399 cw(c224.375,161.5) 222.448,163.6 226.302,163.6 cw(c224.375,161.5) 222.25,159.601
no net on Bottom Solder "BOTTOMSOLDER283" (solid, pour order 0): 233.552,163.6 cw(c231.625,161.5) 233.75,163.399 233.75,159.601 cw(c231.625,161.5) 229.698,163.6
no net on Bottom Solder "BOTTOMSOLDER284" (solid, pour order 0): 233.75,154.601 cw(c231.625,156.5) 233.75,158.399
no net on Bottom Solder "BOTTOMSOLDER285" (solid, pour order 0): 193.05,160 ccw(c195,160) 196.95,160 ccw(c195,160)
no net on Bottom Solder "BOTTOMSOLDER286" (solid, pour order 0): 23.05,160 ccw(c25,160) 26.95,160 ccw(c25,160)
no net on Bottom Solder "BOTTOMSOLDER287" (solid, pour order 0): 23.05,92.5 ccw(c25,92.5) 26.95,92.5 ccw(c25,92.5)
no net on Bottom Solder "BOTTOMSOLDER288" (solid, pour order 0): 23.05,25 ccw(c25,25) 26.95,25 ccw(c25,25)
no net on Bottom Solder "BOTTOMSOLDER289" (solid, pour order 0): 117.66,87.438 116.383,90.52 cw(c117.03,90.787) 117.677,91.055 119.007,87.845 cw(c118.36,87.577) 119.06,87.577 119.06,84.102 cw(c118.36,84.102) 117.66,84.102
no net on Bottom Solder "BOTTOMSOLDER290" (solid, pour order 0): 124.423,91.606 cw(c125.07,91.874) 124.37,91.874 124.37,95.907 cw(c125.07,95.907) 125.77,95.907 125.77,92.013 127.26,88.415 cw(c126.614,88.147) 125.967,87.879
no net on Bottom Solder "BOTTOMSOLDER291" (solid, pour order 0): 179.66,87.438 178.383,90.52 cw(c179.03,90.787) 179.677,91.055 181.007,87.845 cw(c180.36,87.577) 181.06,87.577 181.06,84.102 cw(c180.36,84.102) 179.66,84.102
no net on Bottom Solder "BOTTOMSOLDER292" (solid, pour order 0): 186.423,91.606 cw(c187.07,91.874) 186.37,91.874 186.37,95.907 cw(c187.07,95.907) 187.77,95.907 187.77,92.013 189.26,88.415 cw(c188.614,88.147) 187.967,87.879
no net on Bottom Solder "BOTTOMSOLDER293" (solid, pour order 0): 241.66,87.438 240.383,90.52 cw(c241.03,90.787) 241.677,91.055 243.007,87.845 cw(c242.36,87.577) 243.06,87.577 243.06,84.102 cw(c242.36,84.102) 241.66,84.102
no net on Bottom Solder "BOTTOMSOLDER294" (solid, pour order 0): 248.423,91.606 cw(c249.07,91.874) 248.37,91.874 248.37,95.907 cw(c249.07,95.907) 249.77,95.907 249.77,92.013 251.26,88.415 cw(c250.614,88.147) 249.967,87.879
no net on Bottom Solder "BOTTOMSOLDER295" (solid, pour order 0): 58,150.3 cw(c58,151) 57.3,151 cw(c58,151) 58,151.7 63,151.7 cw(c63,151) 63.7,151 cw(c63,151) 63,150.3

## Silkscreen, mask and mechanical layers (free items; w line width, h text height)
Top Overlay:
  drawing of 499 lines, arcs and shapes, not listed
  text "W18V" at 110.79,162.16 h0.71
  text "W5V" at 111.14,158.66 h0.71
  text "WGND" at 110.79,155.16 h0.71
  text "DC Input" at 114.503,149.602 h1.8
  text "W-2V" at 112.94,149.29 h0.71 r90
  text "DC Input" at 172.54,149.225 h1.8
  text "U" at 211.425,146.75 h3.15
  text "V" at 226.425,146.75 h3.15
  text "W" at 241.425,146.75 h3.15
  text "-" at 121.425,145.025 h3.5
  text "+" at 175.425,144.4 h3.5
  text "V18V" at 110.79,142.06 h0.71
  text "AC Output" at 212.385,139.75 h3.4
  text "V5V" at 111.24,138.56 h0.71
  text "VGND" at 110.79,135.06 h0.71
  text "FG" at 266.25,133.17 h3.15 r90
  text "G_CPH" at 20.84,131.86 h0.71
  text "V-2V" at 110.79,131.56 h0.71
  text "G_CPL" at 44.14,127.14 h0.71 r90
  text "J5(UH),J7(VH),J9(WH),J11(BL)" at 109.258,124.155 h1.2
  text "S_CPH" at 38.14,123.46 h0.71
  text "GateVoltage" at 109.131,121.92 h1.2
  text "A20V" at 20.59,120.16 h0.71
  text "20V/0V" at 113.625,118.825 h0.89
  text "18V/-2V" at 131.79,118.825 h0.89
  text "B5V" at 59.14,114.24 h0.71 r90
  text "U5V" at 76.34,114.14 h0.71 r90
  text "B-2V" at 52.14,113.79 h0.71 r90
  text "BGND" at 55.64,113.69 h0.71 r90
  text "B18V" at 62.64,113.69 h0.71 r90
  text "U-2V" at 69.34,113.69 h0.71 r90
  text "UGND" at 72.84,113.69 h0.71 r90
  text "U18V" at 79.84,113.69 h0.71 r90
  text "AGND" at 20.79,104.26 h0.71
  text "G_VL" at 191.84,76.69 h0.71 r90
  text "G_WH" at 228.74,76.69 h0.71 r90
  text "G_WL" at 253.84,76.69 h0.71 r90
  text "G_VH" at 166.84,76.39 h0.71 r90
  text "G_UL" at 129.84,75.79 h0.71 r90
  text "G_UH" at 104.94,75.69 h0.71 r90
  text "W_OUT" at 211.94,75.16 h0.71
  text "U_OUT" at 87.84,75.06 h0.71
  text "V_OUT" at 149.74,74.96 h0.71
  text "S_UH" at 88.39,72.06 h0.71
  text "S_WH" at 212.39,72.06 h0.71
  text "S_VH" at 150.29,71.96 h0.71
  text "S_UL" at 111.89,71.86 h0.71
  text "S_VL" at 174.09,71.66 h0.71
  text "S_WL" at 236.09,71.66 h0.71
  text "A20V" at 40.04,66.79 h0.71 r90
  text "AGND" at 39.84,55.59 h0.71 r90
  text "DC Input" at 31.14,51.425 h1.8
  text "VREF2R5V" at 60.14,47.29 h0.71 r90
  text "A5V" at 40.24,47.04 h0.71 r90
  text "ADU" at 73.44,44.46 h0.71
  text "D5V" at 40.24,42.24 h0.71 r90
  text "THM2" at 180.34,41.49 h0.71 r90
  text "T_RY" at 192.49,40.76 h0.71
  text "Control Input" at 139.565,31.825 h1.8
  text "UL" at 122.29,31.46 h0.71
  text "VL" at 126.19,31.46 h0.71
  text "VDC" at 42.44,31.34 h0.71 r90
  text "WL" at 134.19,30.66 h0.71
  text "ADW" at 210.14,30.54 h0.71 r90
  text "DGND" at 34.74,29.89 h0.71 r90
  text "ADB" at 58.34,29.74 h0.71 r90
  text "ADV" at 196.94,29.54 h0.71 r90
  text "WH" at 133.29,27.46 h0.71
  text "T_HS" at 190.79,27.46 h0.71
  text "nEMG" at 73.69,27.36 h0.71
  text "VH" at 126.29,27.36 h0.71
  text "UH" at 124.64,26.89 h0.71 r90
  text "BRK" at 115.74,26.86 h0.71
  text "THM1" at 169.79,26.86 h0.71
  text "SiC MOSFET Inverter" at 214.36,24.8 h2.2
Bottom Overlay:
  lines w0.2: 147.966,144.9 152.034,144.9 ; 147.966,150.1 152.034,150.1 ; 147.966,151.4 152.034,151.4 ; 147.966,156.6 152.034,156.6
Mechanical 3:
  lines w0.013: 20.006,20.006 270.006,20.006 270.006,165.006 20.006,165.006 20.006,20.006 ; 58.006,150.506 cw(c58.006,151.006) 58.006,151.506 63.006,151.506 cw(c63.006,151.006) 63.006,150.506 60.256,150.506 58.006,150.506 ; 116.575,90.602 cw(c117.036,90.794) 117.498,90.985 118.828,87.775 cw(c118.366,87.583) 118.866,87.583 118.866,84.108 cw(c118.366,84.108) 117.866,84.108 117.866,87.484 116.575,90.602 ; 124.576,91.88 ccw(c125.076,91.88) 124.614,91.689 126.158,87.962 ccw(c126.62,88.153) 127.082,88.345 125.576,91.979 125.576,95.914 ccw(c125.076,95.914) 124.576,95.914 124.576,91.88 ; 178.575,90.602 cw(c179.036,90.794) 179.498,90.985 180.828,87.775 cw(c180.366,87.583) 180.866,87.583 180.866,84.108 cw(c180.366,84.108) 179.866,84.108 179.866,87.484 178.575,90.602 ; 186.576,91.88 ccw(c187.076,91.88) 186.614,91.689 188.158,87.962 ccw(c188.62,88.153) 189.082,88.345 187.576,91.979 187.576,95.914 ccw(c187.076,95.914) 186.576,95.914 186.576,91.88 ; 240.575,90.602 cw(c241.036,90.794) 241.498,90.985 242.828,87.775 cw(c242.366,87.583) 242.866,87.583 242.866,84.108 cw(c242.366,84.108) 241.866,84.108 241.866,87.484 240.575,90.602 ; 248.576,91.88 ccw(c249.076,91.88) 248.614,91.689 250.158,87.962 ccw(c250.62,88.153) 251.082,88.345 249.576,91.979 249.576,95.914 ccw(c249.076,95.914) 248.576,95.914 248.576,91.88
